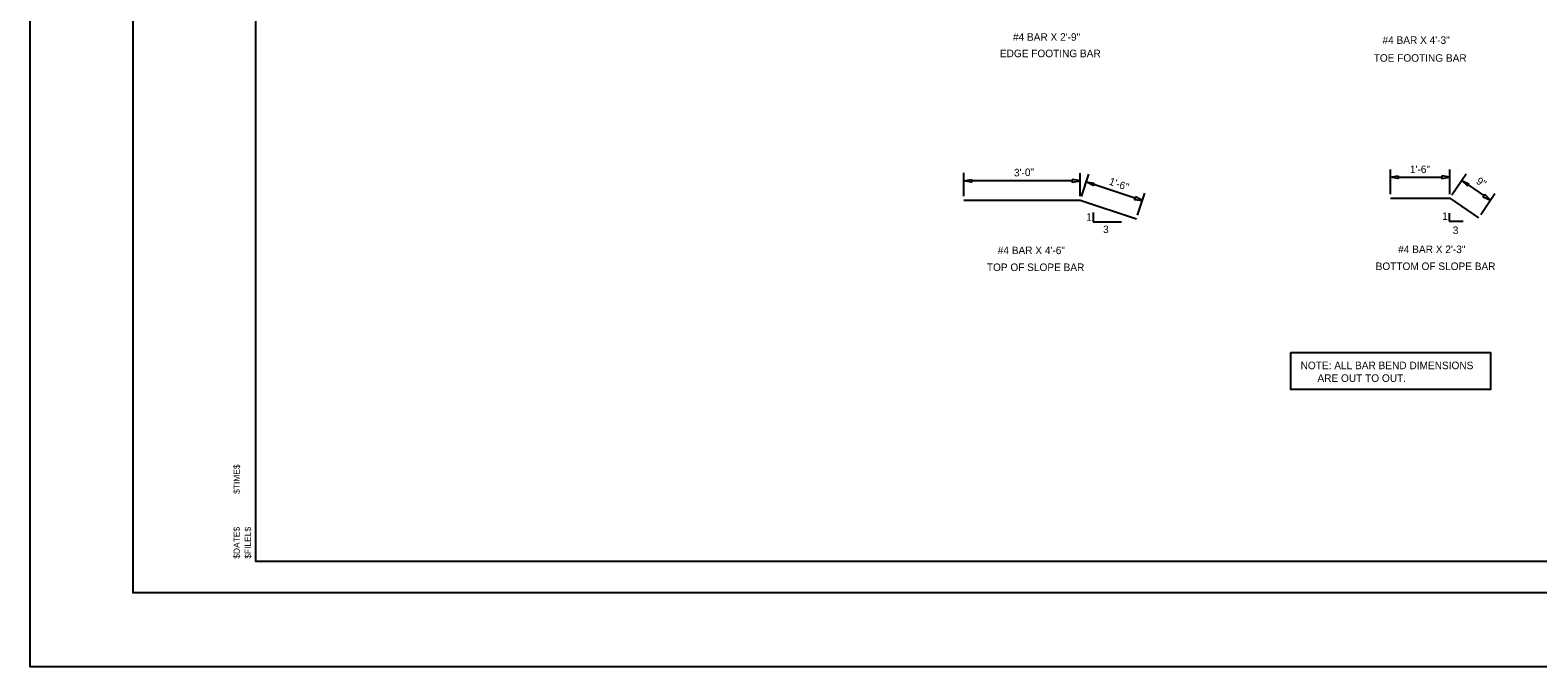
# Model space of a CAD drawing. Extents: x 570 to 2153298, y 726 to 139926.
# Drawn here: x 2153141.23 to 2153165.19, y 139597.62 to 139607.73 of the extents above; entities that cross this region are included whole.
import ezdxf

# ---------------------------------------------------------------- set-up
doc = ezdxf.new("R2010")
doc.units = 0
for name, color, linetype in [('4', 7, 'Continuous'), ('6', 7, 'Continuous'), ('PR_Dimensions', 7, 'Continuous'), ('SHT_Plot_Shape_Full', 7, 'Continuous'), ('SHT_Plot_Shape_Half', 7, 'Continuous'), ('SHT_Plot_Stamp', 7, 'Continuous'), ('SHT_Sheet_Border', 7, 'Continuous'), ('SHT_Standard_Sheet_Txt', 7, 'Continuous'), ('T', 7, 'Continuous')]:
    doc.layers.add(name, color=color, linetype=linetype)

# ---------------------------------------------------------------- blocks, each defined once
blk = doc.blocks.new('Stamp_Plot_Stamp')
at = {"layer": 'SHT_Plot_Stamp'}
for s, p in [('$TIME$', (1.695, 1.572)), ('$DATE$', (1.695, 0.542)), ('$FILEL$', (1.873, 0.542))]:
    blk.add_text(s, height=0.1, rotation=90, dxfattribs=at).set_placement(p)

msp = doc.modelspace()

# ---------------------------------------------------------------- linework, layer by layer
at = {"layer": '4'}
for p, q in [((2153156.068, 139605.035), (2153157.916, 139605.035)), ((2153157.916, 139605.035), (2153158.81, 139604.737))]:
    msp.add_line(p, q, dxfattribs=at)
msp.add_lwpolyline([(2153162.849, 139605.067), (2153163.791, 139605.067), (2153164.249, 139604.754)], dxfattribs=at)
at = {"layer": '6'}
for p, q in [((2153156.066, 139605.099), (2153156.066, 139605.466)), ((2153157.916, 139605.097), (2153157.916, 139605.465)), ((2153157.936, 139605.094), (2153158.052, 139605.444)), ((2153162.849, 139605.129), (2153162.849, 139605.523)), ((2153162.974, 139605.398), (2153163.665, 139605.398)), ((2153163.791, 139605.129), (2153163.791, 139605.523)), ((2153163.826, 139605.119), (2153164.052, 139605.451)), ((2153157.79, 139605.339), (2153156.193, 139605.339)), ((2153158.787, 139605.066), (2153158.132, 139605.285)), ((2153158.829, 139604.796), (2153158.946, 139605.146)), ((2153164.085, 139605.276), (2153164.337, 139605.105)), ((2153164.285, 139604.806), (2153164.511, 139605.138)), ((2153158.124, 139604.837), (2153158.124, 139604.688)), ((2153158.124, 139604.688), (2153158.573, 139604.688)), ((2153163.784, 139604.825), (2153163.784, 139604.7)), ((2153163.784, 139604.7), (2153164.004, 139604.7))]:
    msp.add_line(p, q, dxfattribs=at)
for points in [[(2153156.191, 139605.361), (2153156.191, 139605.319), (2153156.066, 139605.34)], [(2153157.79, 139605.36), (2153157.79, 139605.318), (2153157.916, 139605.339)], [(2153162.974, 139605.418), (2153162.974, 139605.377), (2153162.849, 139605.398)], [(2153163.665, 139605.418), (2153163.665, 139605.377), (2153163.791, 139605.398)], [(2153158.138, 139605.305), (2153158.125, 139605.265), (2153158.013, 139605.324)], [(2153164.097, 139605.293), (2153164.074, 139605.259), (2153163.982, 139605.347)], [(2153164.349, 139605.122), (2153164.325, 139605.087), (2153164.441, 139605.034)], [(2153158.794, 139605.086), (2153158.78, 139605.046), (2153158.906, 139605.026)]]:
    msp.add_lwpolyline(points, close=True, dxfattribs=at)
at = {"layer": 'PR_Dimensions'}
msp.add_lwpolyline([(2153161.266, 139602.614), (2153164.441, 139602.614), (2153164.441, 139602.025), (2153161.266, 139602.025)], close=True, dxfattribs=at)
at = {"layer": 'SHT_Plot_Shape_Full'}
msp.add_lwpolyline([(2153141.225, 139621.622), (2153177.225, 139621.622), (2153177.225, 139597.622), (2153141.225, 139597.622)], close=True, dxfattribs=at)
at = {"layer": 'SHT_Plot_Shape_Half'}
msp.add_lwpolyline([(2153142.863, 139620.797), (2153176.863, 139620.797), (2153176.863, 139598.797), (2153142.863, 139598.797)], close=True, dxfattribs=at)
at = {"layer": 'SHT_Sheet_Border'}
msp.add_lwpolyline([(2153176.313, 139599.297), (2153144.813, 139599.297), (2153144.813, 139620.297), (2153176.313, 139620.297)], close=True, dxfattribs=at)

# ---------------------------------------------------------------- block references
at = {"layer": 'SHT_Standard_Sheet_Txt'}
msp.add_blockref('Stamp_Plot_Stamp', (2153142.863, 139598.797), dxfattribs=at)

# ---------------------------------------------------------------- texts
at = {"layer": 'T'}
for s, height, p in [('#4 BAR X 2\'-9"', 0.12, (2153156.848, 139607.565)), ('#4 BAR X 4\'-3"', 0.12, (2153162.723, 139607.516)), ('EDGE FOOTING BAR', 0.11979, (2153156.641, 139607.304)), ('TOE FOOTING BAR', 0.11979, (2153162.583, 139607.232)), ('1\'-6"', 0.12, (2153163.158, 139605.463)), ('1', 0.12, (2153158.013, 139604.707)), ('1', 0.12, (2153163.673, 139604.72)), ('3', 0.12, (2153158.281, 139604.51)), ('3', 0.12, (2153163.839, 139604.496)), ('#4 BAR X 4\'-6"', 0.12, (2153156.606, 139604.176)), ('#4 BAR X 2\'-3"', 0.12, (2153162.972, 139604.193)), ('TOP OF SLOPE BAR', 0.11979, (2153156.434, 139603.908)), ('BOTTOM OF SLOPE BAR', 0.11979, (2153162.614, 139603.924)), ('NOTE: ALL BAR BEND DIMENSIONS        ', 0.12, (2153161.421, 139602.349)), ('      ARE OUT TO OUT.', 0.12, (2153161.421, 139602.147))]:
    msp.add_text(s, height=height, dxfattribs=at).set_placement(p)
for s, rotation, p in [('3\'-0"', 1.5677, (2153156.866, 139605.41)), ('1\'-6"', 340.8033, (2153158.364, 139605.284)), ('9"', 325.7113, (2153164.2, 139605.309))]:
    msp.add_text(s, height=0.12, rotation=rotation, dxfattribs=at).set_placement(p)

doc.saveas('drawing.dxf')
